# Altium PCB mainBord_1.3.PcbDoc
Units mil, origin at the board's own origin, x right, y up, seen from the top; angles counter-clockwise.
Board outline 3937.01 x 3149.61 mil, 2 copper layers (Top Layer, Bottom Layer); 51 components, 86 nets, 362 pads, 341 vias.
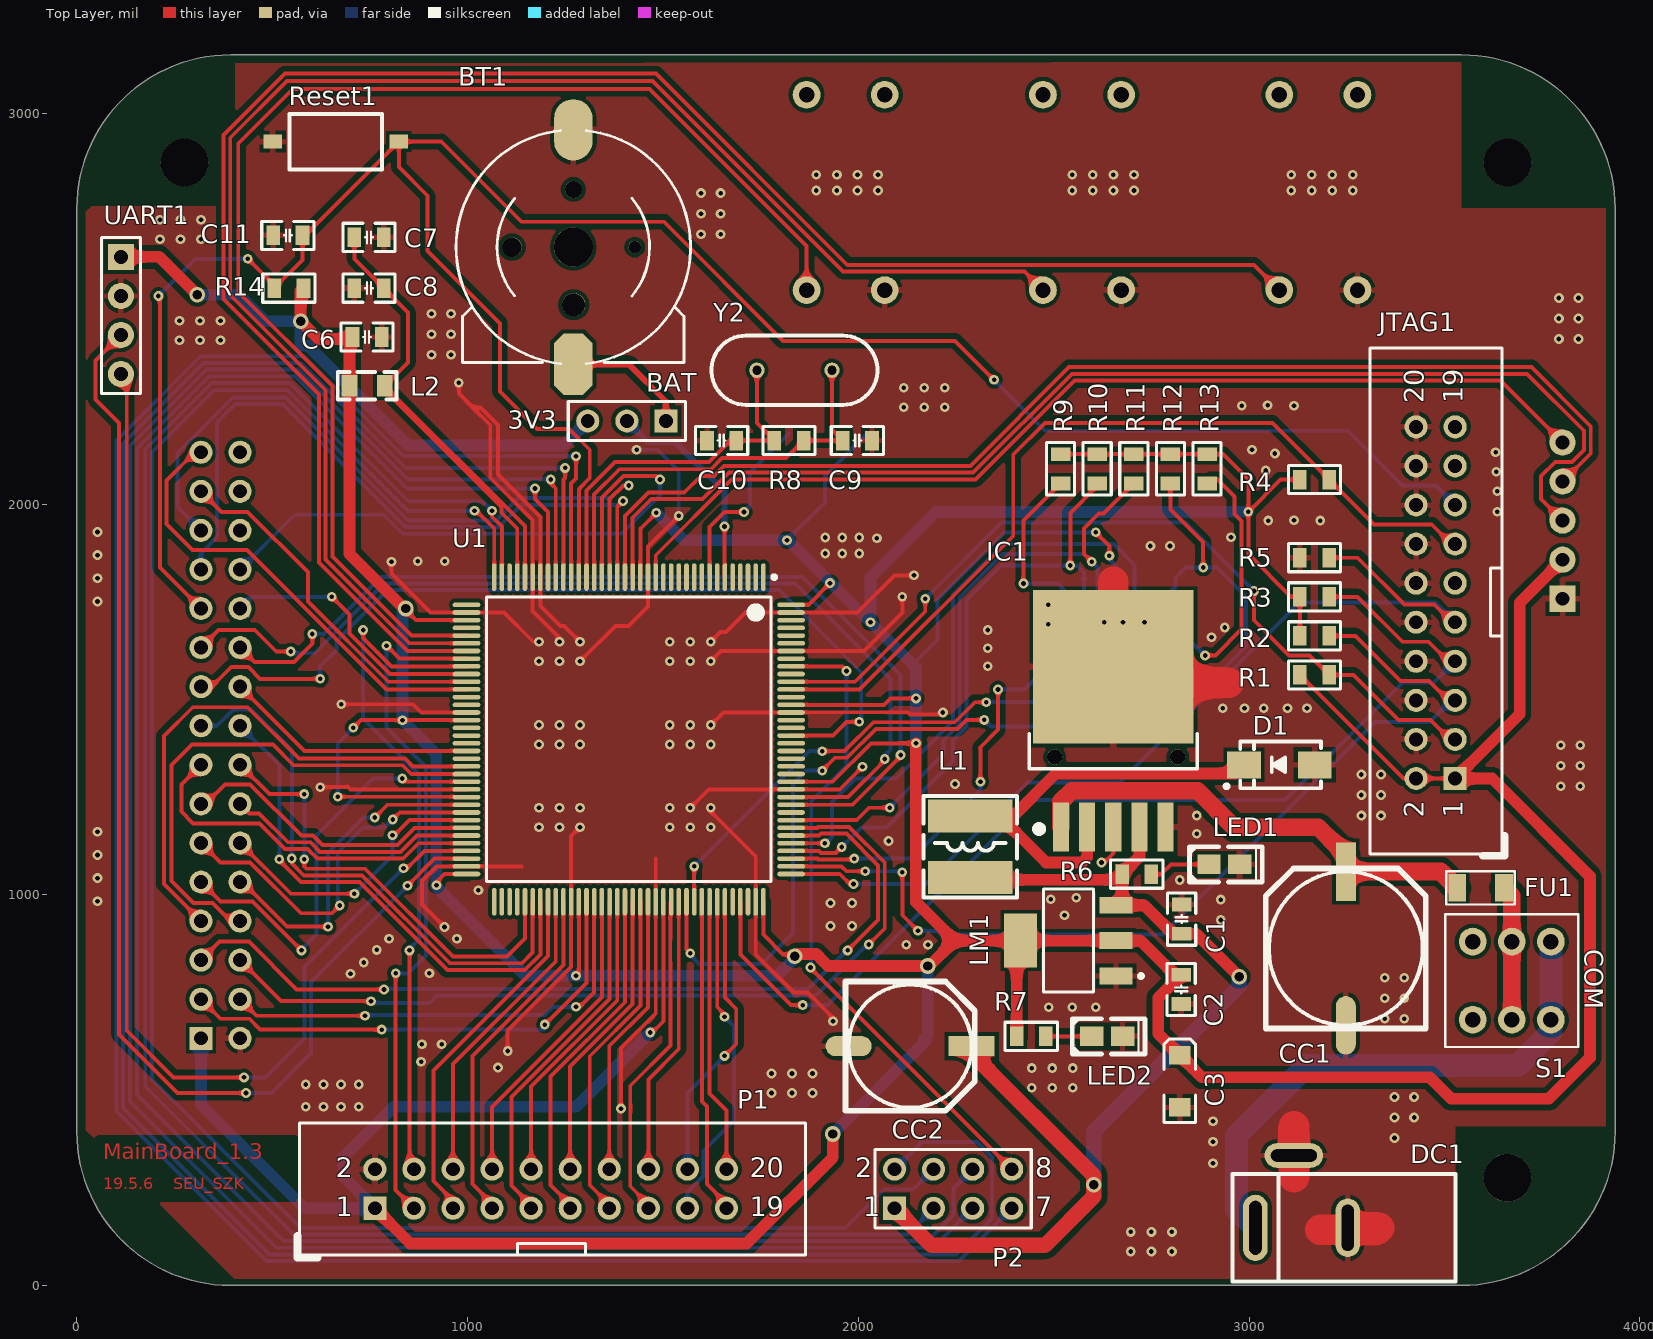
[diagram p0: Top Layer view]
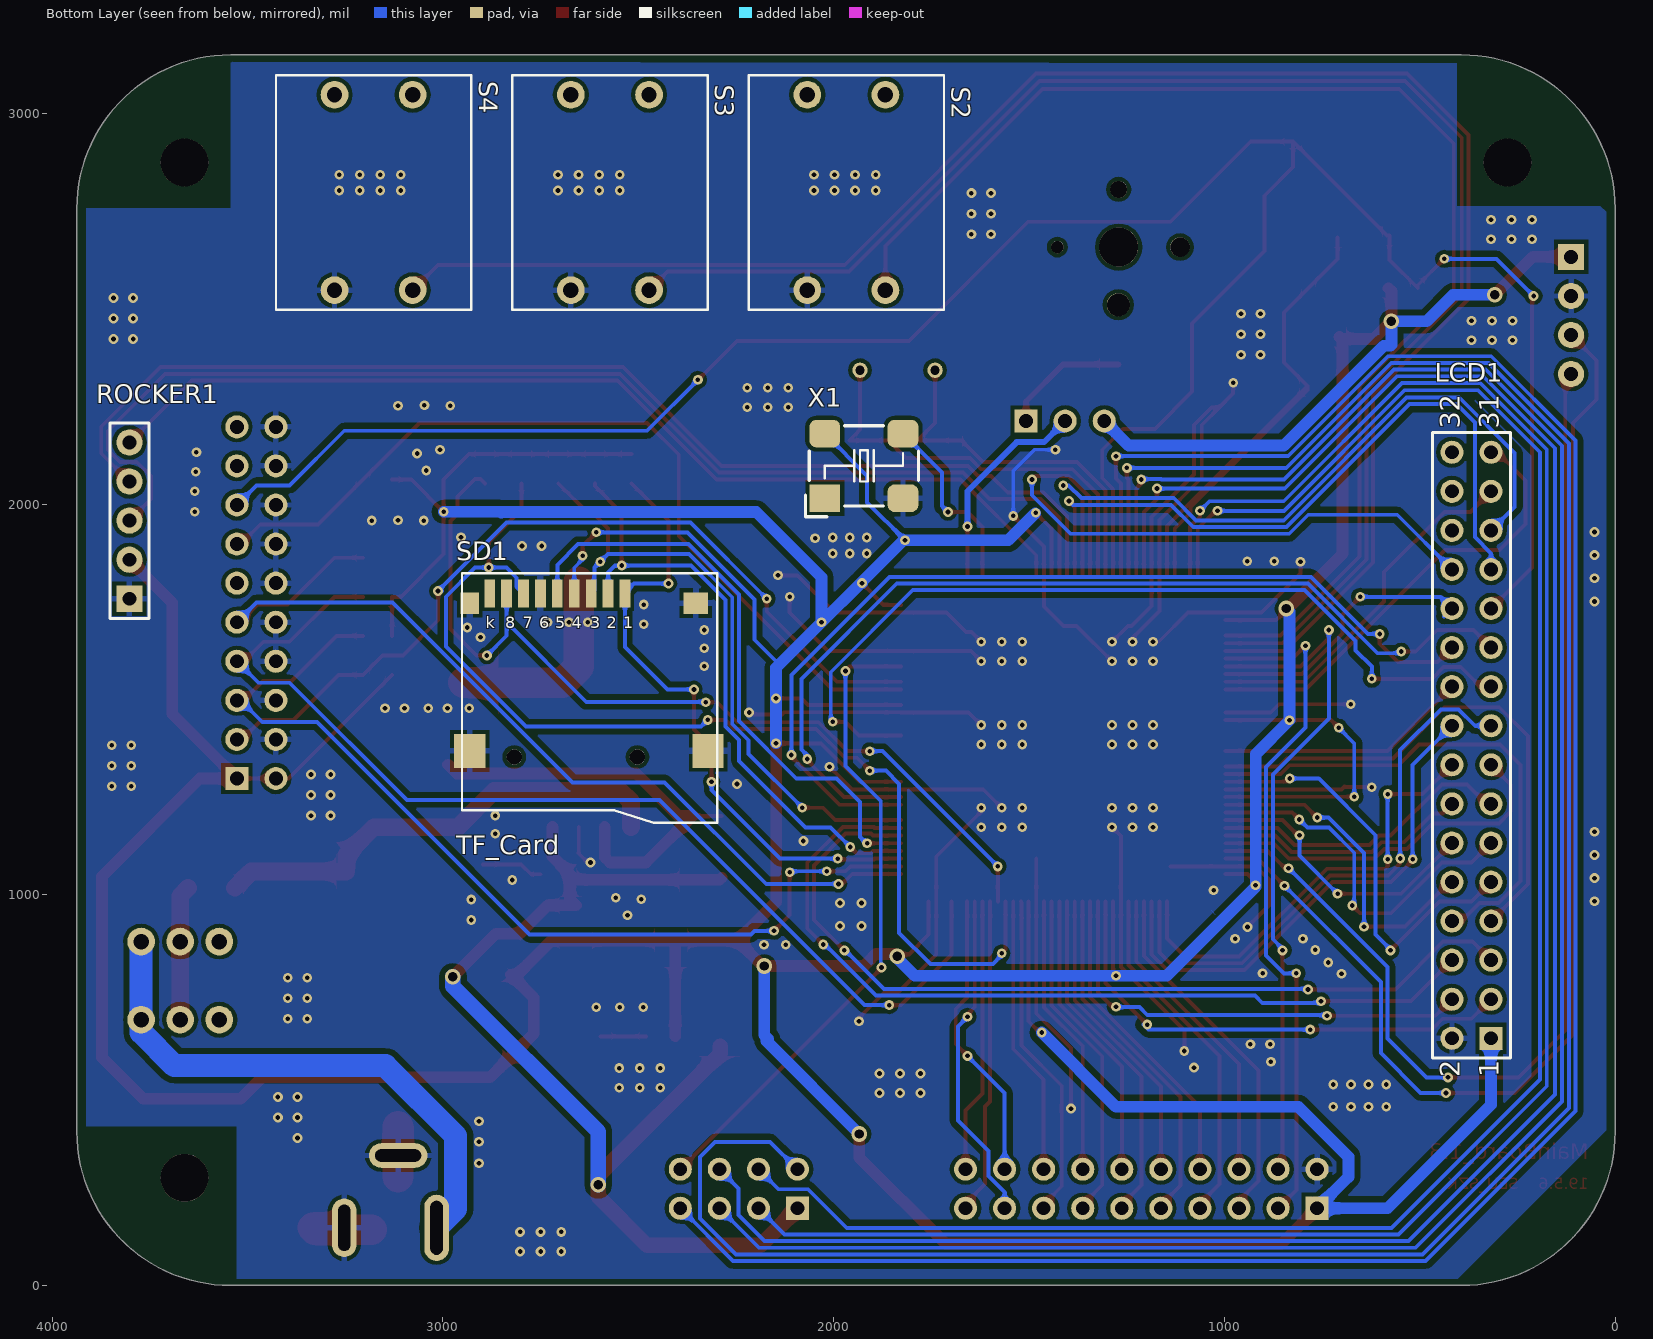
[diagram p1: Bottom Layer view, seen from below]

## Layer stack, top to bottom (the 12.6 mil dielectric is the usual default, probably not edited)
Top Solder: solder mask 0.4, Solder Resist, Dk 3.5
Top Layer: signal copper 1.4
Dielectric 1: dielectric 12.6, FR-4, Dk 4.8
Bottom Layer: signal copper 1.4
Bottom Solder: solder mask 0.4, Solder Resist, Dk 3.5

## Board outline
0,393.7 0,2755.91 cw(c393.7,2755.91) 393.7,3149.61 3543.31,3149.61 cw(c3543.31,2755.91) 3937.01,2755.91 3937.01,393.7 cw(c3543.31,393.7) 3543.31,0 393.7,0 cw(c393.7,393.7)

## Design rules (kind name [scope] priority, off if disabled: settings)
Clearance [InNamedPolygon('GND_L02_P017')] p1: gap=10 ignorepadtopadclearanceinfootprint=FALSE except(0: Arc-Hole Track-Hole SMDPad-Hole THPad-Hole Via-Hole Fill-Hole Poly-Hole Region-Hole Text-Hole; 15: Arc-Fill Arc-Poly Arc-Region Track-Fill Track-Poly Track-Region)
Clearance putuo [InNamedPolygon('Bottom Layer-No Net')] p2: gap=10 ignorepadtopadclearanceinfootprint=FALSE except(0: Arc-Hole Track-Hole SMDPad-Hole THPad-Hole Via-Hole Fill-Hole Poly-Hole Region-Hole Text-Hole; 15: Arc-Fill Arc-Poly Arc-Region Track-Fill Track-Poly Track-Region)
Clearance Clearance_1 [All] p3: gap=7 ignorepadtopadclearanceinfootprint=FALSE except(0: Via-Hole Fill-Hole Poly-Hole Region-Hole Text-Hole)
MinimumSolderMaskSliver [All] p1: minsoldermaskwidth=7
PolygonConnect [All] p1: thpad.connectstyle=Relief thpad.reliefconductorwidth=15 thpad.reliefentries=4 thpad.polygonreliefangle="90 Angle" thpad.airgapwidth=10 smdpad.connectstyle=Relief smdpad.reliefconductorwidth=15 smdpad.reliefentries=4 smdpad.polygonreliefangle="90 Angle" smdpad.airgapwidth=10 via.connectstyle=Direct via.reliefconductorwidth=10 via.reliefentries=4 via.polygonreliefangle="90 Angle" via.airgapwidth=10
RoomDefinition mainBord [InComponentClass('mainBord')] p1: confinementstyle=ConfineIn formatcopy=TRUE lockcomponents=FALSE outline 393.7,3149.61 0,2755.91 0,393.7 393.7,0 3543.31,0 3937.01,393.7 3937.01,2755.91 3543.31,3149.61
RoutingVias [All] p1: holewidth=12 width=25 viastyle="Through Hole" minholewidth=8 minwidth=20 maxholewidth=24 maxwidth=40
SilkToSilkClearance [All] p1 off: silktosilkclearance=10
SilkToSolderMaskClearance [IsPad] p1 off: minsilkscreentomaskgap=10 clearancetoexposedcopper=TRUE
SolderMaskExpansion [All] p1: expansion=4
Width 12V [InNetClass('12V')] p1: maxlimit=78.74 minlimit=39.37 preferedwidth=59.06 minimp=50.000000 maximp=50.000000 favimp=50.000000
Width 5V [InNet('5V')] p2: maxlimit=39.37 minlimit=30 preferedwidth=39.37 minimp=50.000000 maximp=50.000000 favimp=50.000000
Width 3.3V [InNet('3.3V')] p3: maxlimit=39.37 minlimit=10 preferedwidth=30 minimp=50.000000 maximp=50.000000 favimp=50.000000
Width [All] p4: maxlimit=78.74 minlimit=10 preferedwidth=10 minimp=50.000000 maximp=50.000000 favimp=50.000000
27 further rules are at their usual default settings.

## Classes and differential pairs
polygon class PolygonClass_1: GND_L02_P007

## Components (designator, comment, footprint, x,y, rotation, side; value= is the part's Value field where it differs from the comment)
3V3 "Header 3" HDR1X3 1507.6,2212.6 r180 top (schematic designator P3)
BT1 "CR220" battery 1270.95,2556.19 r180 top
C1 "100nf" "C 0805_L" 2827.6,937.6 r90 top value=100nF
C2 "100nf" "C 0805_L" 2826.49,757.6 r270 top value=100nF
C3 "10uf" "CD A(3216)" 2822.6,522.6 r270 top value=10uF
C6 "100nf" "C 0805_L" 742.6,2427.6 r0 top value=100pF
C7 "100nf" "C 0805_L" 747.6,2682.6 r0 top value=100nF
C8 "100nf" "C 0805_L" 747.6,2552.6 r180 top value=100nF
C9 "22pf" "C 0805_L" 1997.6,2162.6 r180 top value=22pF
C10 "22pf" "C 0805_L" 1650.2,2162.6 r0 top value=22pF
C11 "100nf" "C 0805_L" 540.2,2687.6 r0 top value=100nF
CC1 "680uf" "CM F(10*10.2)" 3247.6,862.6 r90 top
CC2 "220uf" "CM E(8*10.2)" 2132.6,612.6 r0 top
D1 "SS14" SMA 3077.6,1332.6 r180 top
DC1 "DC005" DC005座 3252.6,147.6 r180 top
FU1 "200mA" 1206_R 3592.6,1017.6 r180 top
IC1 "LM2596-5.0V" TO263-5A 2652.6,1173.35 r0 top
JTAG1 "JTAG" JTAG20 3527.6,1297.6 r90 top
L1 "Inductor" CD54 2286.66,1122.6 r270 top value=33uH
L2 "Inductor" "L 0805" 742.6,2302.6 r0 top value=4.7uH
LCD1 "TFTLCD" HDR2X16 317.6,632.6 r90 bottom
LED1 "LED2" LED-0805 2897.6,1077.6 r0 top
LED2 "LED2" LED-0805 2597.6,637.6 r0 top
LM1 "LM1117DT-3.3" SOT-223 2537.6,882.6 r90 top
P1 "OUT1" JTAG20 762.6,197.6 r0 top
P2 "OUT2" HDR2X4 2092.6,197.6 r0 top
R1 "10K" "R 0805_L" 3167.6,1562.6 r180 top
R2 "10K" "R 0805_L" 3167.6,1662.6 r180 top
R3 "10K" "R 0805_L" 3167.6,1762.6 r180 top
R4 "10K" "R 0805_L" 3167.6,2062.6 r180 top
R5 "10K" "R 0805_L" 3167.6,1862.6 r0 top
R6 "1K" "R 0805_L" 2712.6,1052.6 r180 top
R7 "1K" "R 0805_L" 2442.6,637.6 r180 top
R8 "1M" "R 0805_L" 1822.6,2162.6 r0 top
R9 "5K" "R 0805_L" 2517.6,2090.19 r270 top
R10 "5K" "R 0805_L" 2611.35,2090.19 r270 top
R11 "5K" "R 0805_L" 2705.1,2090.19 r270 top
R12 "5K" "R 0805_L" 2798.85,2090.19 r270 top
R13 "5K" "R 0805_L" 2892.6,2090.19 r270 top
R14 "1K" "R 0805_L" 542.6,2552.6 r0 top
Reset1 "SW-PB" switch_1 662.6,2927.6 r180 top
ROCKER1 "RK" HDR2.54-M-LI-5P 3802.6,1957.6 r90 bottom
S1 "SW-DPDT" 按键开关-1 3772.6,880.2 r180 top
S2 "SW-PB" 微动开关-大-1-绿 2067.6,2547.6 r180 bottom
S3 "SW-PB" 微动开关-大-1-绿 2672.6,2547.6 r180 bottom
S4 "SW-PB" 微动开关-大-1-绿 3277.6,2547.6 r180 bottom
SD1 "TF_Card" "Micro SD" 2660.08,1352.6 r180 bottom
U1 "STM32F103ZET6" STM-LQFP144_N 1412.6,1397.6 r270 top
UART1 "Header 4" HDR2.54-LI-4P 112.6,2482.6 r270 top
X1 "32.768k" "OSC 7050-4P" 1922.6,2097.6 r180 bottom
Y2 "XTAL" HC-49S 1836.54,2342.6 r0 top

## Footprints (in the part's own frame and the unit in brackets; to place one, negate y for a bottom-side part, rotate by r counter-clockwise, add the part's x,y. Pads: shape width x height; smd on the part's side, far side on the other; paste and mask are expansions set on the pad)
1206_R [mil]
  rect 45x70 smd: 1(-60,0) 2(60,0)
  silkscreen extent -88,-43 88,43, body extent -71,-28 71,28, height 30
battery [mm]
  round 0.813 hole 0.813: 0(-3.979,-2.576)
  round 1.5 hole 1.5: 0(-0.016,1.174)
  round 2.54 hole 2.54: 0(0.009,-2.576)
  round 1.1 hole 1.1: 0(0.009,-6.326)
  round 1.27 hole 1.27: 0(3.997,-2.576)
  oct 2.5x4 smd: GBAT(0.009,5.044)
  oval 2.5x4 smd: VBAT(0.009,-10.196)
  silkscreen extent -7.61,-10.15 7.63,5
"C 0805_L" [mil] "无极性贴片电容"
  rect 35x50 smd: 1(-37.4,0) 2(37.4,0)
  silkscreen extent -67,-36 67,36, body extent -39,-24 39,24, height 20
CD54 [mm] "5.8*5.2*4.5mm（长宽高）"
  rect 2.15x5.5 smd: 1(-2,0) 2(2,0)
  silkscreen extent -3.3,-3.05 3.3,3.05, body extent -2.87,-2.5 2.87,2.5, height 4
"CD A(3216)" [mm] "长3.2mm，宽1.6mm，厚1.6mm"
  rect 1.2x1.4 smd: 1(-1.7,0) 2(1.7,0)
  silkscreen extent -2.74,-1.02 2.67,1.02, body extent -1.6,-0.8 1.6,0.8, height 1.6
"CM E(8*10.2)" [mm] "贴片电解电容，直径8mm，高10.2mm"
  rect 3x1.3 smd: 1(4,0)
  oval 3x1.3 smd: 2(-4,0)
  silkscreen extent -4.2,-4.2 4.2,4.2, body extent -4.5,-4.15 4.5,4.15, height 10.2
"CM F(10*10.2)" [mm] "贴片电解电容，直径10mm，高10.2mm"
  rect 3.8x1.3 smd: 1(5,0)
  oval 3.8x1.3 smd: 2(-5,0)
  silkscreen extent -5.2,-5.2 5.2,5.2, body extent -5.8,-5.15 5.8,5.15, height 10.2
DC005座 [mm]
  oval 3.8x1.6 hole 0.8 slot 3 at 0 deg: CON(3.5,-4.7)
  oval 1.6x3.8 hole 0.8 slot 3 at 90 deg: GND(0,0)
  oval 1.6x4.3 hole 0.8 slot 3.5 at 90 deg: VCC(6,0)
  silkscreen extent -7,-3.5 7.49,3.5
HC-49S [mm]
  round 1 hole 0.6: XTAL_1(-2.44,0) XTAL_2(2.44,0)
  silkscreen extent -5.4,-2.25 5.4,2.25
HDR1X3 [mm] "Connector; Header; 3 Position"
  rect 1.5x1.5 hole 0.9: 1(0,0)
  round 1.5 hole 0.9: 2(2.54,0) 3(5.08,0)
  silkscreen extent -1.27,-1.27 6.35,1.27
HDR2.54-LI-4P [mm] "排针，4脚"
  rect 1.7x1.7 hole 0.9: 1(-3.81,0)
  round 1.7 hole 0.9: 2(-1.27,0) 3(1.27,0) 4(3.81,0)
  silkscreen extent -5.08,-1.27 5.08,1.27, body extent -5.08,-1.27 5.08,1.27, height 8.5
HDR2.54-M-LI-5P [mm] "排母，5脚"
  rect 1.7x1.7 hole 0.9: 1(-5.08,0)
  round 1.7 hole 0.9: 2(-2.54,0) 3(0,0) 4(2.54,0) 5(5.08,0)
  silkscreen extent -6.35,-1.27 6.35,1.27, body extent -6.35,-1.27 6.35,1.27, height 8.5
HDR2X4 [mm] "Connector; Header; 4x2 Position"
  rect 1.5x1.5 hole 0.9: 1(0,0)
  round 1.5 hole 0.9: 2(0,2.54) 3(2.54,0) 4(2.54,2.54) 5(5.08,0) 6(5.08,2.54) 7(7.62,0) 8(7.62,2.54)
  silkscreen extent -1.27,-1.27 8.89,3.81
HDR2X16 [mm] "Connector; Header; 16x2 Position"
  rect 1.5x1.5 hole 0.9: 1(0,0)
  round 1.5 hole 0.9: 2(0,2.54) 3(2.54,0) 4(2.54,2.54) 5(5.08,0) 6(5.08,2.54) 7(7.62,0) 8(7.62,2.54) 9(10.16,0) 10(10.16,2.54) 11(12.7,0) 12(12.7,2.54) 13(15.24,0) 14(15.24,2.54) 15(17.78,0) 16(17.78,2.54) 17(20.32,0) 18(20.32,2.54) 19(22.86,0) 20(22.86,2.54) 21(25.4,0) 22(25.4,2.54) 23(27.94,0) 24(27.94,2.54) 25(30.48,0) 26(30.48,2.54) 27(33.02,0) 28(33.02,2.54) 29(35.56,0) 30(35.56,2.54) 31(38.1,0) 32(38.1,2.54)
  silkscreen extent -1.27,-1.27 39.37,3.81
JTAG20 [mm]
  rect 1.5x1.5 hole 0.9: 1(0,0)
  round 1.5 hole 0.9: 2(0,2.54) 3(2.54,0) 4(2.54,2.54) 5(5.08,0) 6(5.08,2.54) 7(7.62,0) 8(7.62,2.54) 9(10.16,0) 10(10.16,2.54) 11(12.7,0) 12(12.7,2.54) 13(15.24,0) 14(15.24,2.54) 15(17.78,0) 16(17.78,2.54) 17(20.32,0) 18(20.32,2.54) 19(22.86,0) 20(22.86,2.54)
  silkscreen extent -5.03,-3.23 27.99,5.54, body extent -5.01,-3.18 27.99,5.62, height 10.9
"L 0805" [mil] "小功率贴片电感"
  rect 40x55 smd: 1(-45,0) 2(45,0)
  silkscreen extent -75,-35 75,35, body extent -39,-24 39,24, height 35
LED-0805 [mil]
  rect 60x50 smd: 1(0,0) 2(78.74,0)
  silkscreen extent -50,-45 136,45
"Micro SD" [mm]
  round 1 hole 1 unplated: 0(-4,0) 0(4,0)
  rect 0.7x1.8 smd: 1(3.2,10.627) 2(2.1,10.627) 3(1,10.627) 4(-0.1,10.627) 5(-1.2,10.627) 6(-2.3,10.627) 7(-3.4,10.627) 8(-4.5,10.627) 9(-5.6,10.627)
  rect 2.032x2.2 smd: 10(-6.9,0.4) 10(8.6,0.4)
  rect 1.2x1.4 smd: 10(-6.9,10)
  rect 1.6x1.4 smd: 10(7.8,10)
  silkscreen extent -7.4,-4.28 9.2,11.94, body extent 0,0 0,0
"OSC 7050-4P" [mm] "7mm*5mm*1.3mm(长*宽*高)"
  rect 2x1.8 smd: 1(-2.54,-2.1)
  rrect50% 2x1.8 smd: 2(2.54,-2.1) 3(2.54,2.1) 4(-2.54,2.1)
  silkscreen extent -3.81,-3.3 3.56,2.61, body extent -3.5,-2.5 3.5,2.5, height 1.36
"R 0805_L" [mil] "1/8W贴片电阻"
  rect 35x50 smd: 1(-37.4,0) 2(37.4,0)
  silkscreen extent -67,-36 67,36, body extent -39,-25 39,25, height 20
SMA [mm] "4.5x2.6*2.2mm（长宽高，不包括引脚）"
  rect 2.2x1.75 smd: 1(-2.3,0) 2(2.3,0)
  silkscreen extent -2.7,-1.52 3.56,1.52, body extent -2.53,-1.3 2.58,1.3, height 2.15
SOT-223 [mm] "SOT-223/SC-73; 4 Leads; Body 6.7 x 7.3 mm, inc. leads (LxW max)"
  rect 1.1x2.15 smd: 1(-2.3,-3.1) 2(0,-3.1) 3(2.3,-3.1)
  rect 3.5x2.15 smd: 4(0,3.1)
  silkscreen extent -3.35,-4.85 3.35,1.63, body extent -3.25,-3.58 3.25,3.38, height 1.65
STM-LQFP144_N [mm] "Thin QFP, 144-Leads, Body 20x20mm, Pitch 0.5mm, IPC Medium Density"
  oval 1.8x0.3 smd: 1(-10.55,8.75) 2(-10.55,8.25) 3(-10.55,7.75) 4(-10.55,7.25) 5(-10.55,6.75) 6(-10.55,6.25) 7(-10.55,5.75) 8(-10.55,5.25) 9(-10.55,4.75) 10(-10.55,4.25) 11(-10.55,3.75) 12(-10.55,3.25) 13(-10.55,2.75) 14(-10.55,2.25) 15(-10.55,1.75) 16(-10.55,1.25) 17(-10.55,0.75) 18(-10.55,0.25) 19(-10.55,-0.25) 20(-10.55,-0.75) 21(-10.55,-1.25) 22(-10.55,-1.75) 23(-10.55,-2.25) 24(-10.55,-2.75) 25(-10.55,-3.25) 26(-10.55,-3.75) 27(-10.55,-4.25) 28(-10.55,-4.75) 29(-10.55,-5.25) 30(-10.55,-5.75) 31(-10.55,-6.25) 32(-10.55,-6.75) 33(-10.55,-7.25) 34(-10.55,-7.75) 35(-10.55,-8.25) 36(-10.55,-8.75) 73(10.55,-8.75) 74(10.55,-8.25) 75(10.55,-7.75) 76(10.55,-7.25) 77(10.55,-6.75) 78(10.55,-6.25) 79(10.55,-5.75) 80(10.55,-5.25) 81(10.55,-4.75) 82(10.55,-4.25) 83(10.55,-3.75) 84(10.55,-3.25) 85(10.55,-2.75) 86(10.55,-2.25) 87(10.55,-1.75) 88(10.55,-1.25) 89(10.55,-0.75) 90(10.55,-0.25) 91(10.55,0.25) 92(10.55,0.75) 93(10.55,1.25) 94(10.55,1.75) 95(10.55,2.25) 96(10.55,2.75) 97(10.55,3.25) 98(10.55,3.75) 99(10.55,4.25) 100(10.55,4.75) 101(10.55,5.25) 102(10.55,5.75) 103(10.55,6.25) 104(10.55,6.75) 105(10.55,7.25) 106(10.55,7.75) 107(10.55,8.25) 108(10.55,8.75)
  oval 0.3x1.8 smd: 37(-8.75,-10.55) 38(-8.25,-10.55) 39(-7.75,-10.55) 40(-7.25,-10.55) 41(-6.75,-10.55) 42(-6.25,-10.55) 43(-5.75,-10.55) 44(-5.25,-10.55) 45(-4.75,-10.55) 46(-4.25,-10.55) 47(-3.75,-10.55) 48(-3.25,-10.55) 49(-2.75,-10.55) 50(-2.25,-10.55) 51(-1.75,-10.55) 52(-1.25,-10.55) 53(-0.75,-10.55) 54(-0.25,-10.55) 55(0.25,-10.55) 56(0.75,-10.55) 57(1.25,-10.55) 58(1.75,-10.55) 59(2.25,-10.55) 60(2.75,-10.55) 61(3.25,-10.55) 62(3.75,-10.55) 63(4.25,-10.55) 64(4.75,-10.55) 65(5.25,-10.55) 66(5.75,-10.55) 67(6.25,-10.55) 68(6.75,-10.55) 69(7.25,-10.55) 70(7.75,-10.55) 71(8.25,-10.55) 72(8.75,-10.55) 109(8.75,10.55) 110(8.25,10.55) 111(7.75,10.55) 112(7.25,10.55) 113(6.75,10.55) 114(6.25,10.55) 115(5.75,10.55) 116(5.25,10.55) 117(4.75,10.55) 118(4.25,10.55) 119(3.75,10.55) 120(3.25,10.55) 121(2.75,10.55) 122(2.25,10.55) 123(1.75,10.55) 124(1.25,10.55) 125(0.75,10.55) 126(0.25,10.55) 127(-0.25,10.55) 128(-0.75,10.55) 129(-1.25,10.55) 130(-1.75,10.55) 131(-2.25,10.55) 132(-2.75,10.55) 133(-3.25,10.55) 134(-3.75,10.55) 135(-4.25,10.55) 136(-4.75,10.55) 137(-5.25,10.55) 138(-5.75,10.55) 139(-6.25,10.55) 140(-6.75,10.55) 141(-7.25,10.55) 142(-7.75,10.55) 143(-8.25,10.55) 144(-8.75,10.55)
  silkscreen extent -10.67,-9.25 9.25,9.58, body extent -10,-10 10,10, height 1.6
switch_1 [mm]
  rect 1.2x0.9 smd: 1(-4.1,0) 2(4.1,0)
  silkscreen extent -3,-1.8 3,1.82
TO263-5A [mm] "263，5脚晶体管"
  rect 1.05x3.2 smd: 1(-3.4,0) 2(-1.7,0) 3(0,0) 4(1.7,0) 5(3.4,0)
  rect 10.45x10 smd: 3(0,10.414)
  silkscreen extent -5.46,-0.33 5.46,6.04, body extent -5,-0.01 5,13.32, height 4.5
微动开关-大-1-绿 [mm]
  round 1.8 hole 1: 1(0,0) 2(0,12.7) 3(5.08,0) 4(5.08,12.7)
  silkscreen extent -3.81,-1.27 8.89,13.97, body extent -3.46,-0.51 8.54,13.37, height 10
按键开关-1 [mm]
  round 1.8 hole 1: 1(0,0) 2(2.54,0) 3(5.08,0) 4(0,5.08) 5(2.54,5.08) 6(5.08,5.08)
  silkscreen extent -1.78,-1.78 6.86,6.86, body extent -1.71,-1.78 6.79,6.72, height 14.5

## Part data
3V3: "Header, 3-Pin"
BT1: library part Battery, "Multicell Battery"
C1 C2 C6 C7 C8 C9 C10 C11: library part Cap, "Capacitor"
C3: library part "Cap Pol2", "Polarized Capacitor (Axial)"
CC1 CC2: library part CAP-T, "贴片铝解电容"
D1: "肖特基二极管"
FU1: library part FUSE
IC1: library part LM2596-5.0, "DC降压芯片"
JTAG1 P1: library part "Header 10X2", "Header, 10-Pin, Dual row"
L1: Manufacturer="Generic Components"
LCD1: library part MHDR2X16, "Header, 16-Pin, Dual row"
LED1 LED2: "Typical RED, GREEN, YELLOW, AMBER GaAs LED"
LM1: "800mA Low-Dropout Linear Regulator, 3-pin TO-252", Manufacturer="National Semiconductor", PackageTopMarking=NSUZXYTT*LM1117*DT-3.3, PowerWise=N
P2: library part "Header 4X2", "Header, 4-Pin, Dual row"
R1 R2 R3 R4 R5 R6 R7 R8 R9 R10 R11 R12 R13 R14: library part Res2, "Resistor"
Reset1: "Switch"
ROCKER1: library part MHDR1X5, "Header, 5-Pin"
S2 S3 S4: library part 微动开关
SD1: "TF卡座"
U1: "ARM Cortex-M3 32-bit MCU, 512 KB Flash, 64 KB Internal RAM, 112 I/Os, 144-pin LQFP, -40 to 85 degC, Tray", I/Os (High Current)=112, Operating Frequency(F) (Processor speed) (MHz)=72, Supplier Part Number 1=497-6442-ND, Supply Voltage(Vcc) min (V)=2
UART1: "Header, 4-Pin"
X1: library part XTAL-4, "4脚晶振"
Y2: "Crystal Oscillator"

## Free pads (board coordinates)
  round 122.05 hole 122.05 unplated: 2(275.59,2874.02) 3(3661.42,2874.02) 4(3661.42,275.59)

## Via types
v1: diameter 25, hole 12, Top Layer to Bottom Layer, 333 vias
v2: diameter 40, hole 24, Top Layer to Bottom Layer, 8 vias

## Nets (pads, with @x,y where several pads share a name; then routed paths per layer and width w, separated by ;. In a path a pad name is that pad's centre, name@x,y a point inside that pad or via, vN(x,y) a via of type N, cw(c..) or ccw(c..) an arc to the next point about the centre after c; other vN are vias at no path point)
3.3V: 3V3.3 C2.1 C3.1 C6.1 JTAG1.1 JTAG1.2 L2.1 LCD1.1 LM1.2 LM1.4 P1.1 R1.2 R2.2 R3.2 R4.2 R7.2 R9.1 R10.1 R11.1 R12.1 R13.1 R14.2 ROCKER1.2 SD1.4 U1.17 U1.39 U1.52 U1.62 U1.72 U1.84 U1.95 U1.108 U1.121 U1.131 U1.144 UART1.1 X1.4 | length 20624.3
  Top Layer w10: R14.2 R14.2@580.19,2552.59 ; v1(667.6,1250.78) 996.43,1250.78 U1.62 ; v1(707.6,1427.6) 726.81,1446.81 v1(833.39,1446.81) U1.52 ; v2@841.14,1729.18 867.6,1702.72 U1.39 ; v1(920.6,1024.6) 920.6,1032.6 941.11,1053.11 U1.72 ; v1(1277.6,792.6) 1282.6,792.6 1282.6,800.25 1284.65,802.3 U1.84 ; U1.17 1442.13,1937.6 1443.1,1937.6 v1(1483.1,1977.6) ; v1(1467.6,647.6) 1472.6,647.6 1501.18,676.18 U1.95 ; U1.108 1757.09,898.11 1807.6,847.6 1842.6,847.6 v2(1837.6,842.6) ; U1.121 1934.33,1289.33 2032.6,1387.6 v1(2147.6,1387.6) ; U1.131 2065.6,1486.18 2082.02,1502.6 v1(2147.6,1502.6) ; U1.144 1872.09,1742.09 v1(1927.6,1797.6) ; R9.1 R10.1 R11.1 R12.1 R13.1 2933.29,2127.6 2998.18,2062.71 v1@2998.18,1988.14 ; v1(2607.6,1927.6) 2642.6,1892.6 v1(2642.6,1867.6) ; R1.2 3395.21,1297.6 JTAG1.2 JTAG1.1 ; R2.2 R3.2 3107.6,1762.6 2998.18,1872.02 v1(2998.18,1980.11) 3080.68,2062.6 R4.2
  Top Layer w30: UART1.1 210.44,2632.6 v2(307.6,2535.44) ; R14.2 572.6,2545.2 v2(572.6,2467.6) 617.6,2422.6 C6.1@700.2,2422.6 ; C6.1 C6.1@700.2,2422.6 ; P1.1 852.6,107.6 1714.51,107.6 1934.33,327.42 v2(1934.33,387.6) ; v2@839.68,1730.64 697.6,1872.72 L2.1 697.6,2420 C6.1@700.2,2422.6 ; v2@1842.6,847.6 1843.47,848.47 1891.89,848.47 1912.1,828.26 1912.1,828.1 1922.6,817.6 v2(2177.6,817.6) 2177.6,813.88 2246.32,882.6 ; v1(2147.6,1387.6) 2147.33,1387.33 2147.33,981.58 2246.32,882.6 ; R7.2 2405.2,872.25 LM1.4 ; ROCKER1.2 3692.6,1747.6 3692.6,1462.6 JTAG1.1 3622.6,1297.6 3872.6,1047.6 3872.6,582.6 3767.6,477.6 3517.6,477.6 3462.6,532.6 2879.53,532.6 C3.1 2767.6,644.53 2767.6,736.11 C2.1 2810.19,795 2722.6,882.6 LM1.2 LM1.4 ; 2246.32,882.6 LM1.4
  Bottom Layer w10: v1(667.6,1250.78) 667.6,1387.6 v1(707.6,1427.6) ; v1(1817.6,1907.6) 1914.45,2004.45 1914.45,2072.13 X1.4 ; 2142.6,1586.26 2142.6,1592.6 2202.6,1652.6 2202.6,1755.75 2374.45,1927.6 v1(2607.6,1927.6) ; v1(2642.6,1867.6) 2642.6,1858.28 2664.02,1836.86 SD1.4
  Bottom Layer w30: v2(307.6,2535.44) 414.76,2535.44 482.6,2467.6 v2(572.6,2467.6) 572.6,2407.6 575,2405.19 592.23,2405.19 847.82,2149.6 1244.6,2149.6 3V3.3 ; LCD1.1 317.6,462.6 582.6,197.6 P1.1 682.6,277.6 682.6,329.74 810.46,457.6 1277.6,457.6 v1(1467.6,647.6) ; v2(841.64,1732.6) 833.39,1724.34 v1(833.39,1446.81) 920.04,1360.16 v1@920.04,1024.6 ; v1@920.04,1020.16 1147.6,792.6 v1(1277.6,792.6) 1792.6,792.6 1842.6,842.6 v2(1837.6,842.6) ; v1@1484.44,1976.26 1553.1,1907.6 v1(1817.6,1907.6) 1821.26,1907.6 1927.6,1801.26 v1(1927.6,1797.6) 1931.26,1797.6 v1(2031.26,1697.6) ; v2(1934.33,387.6) 2172.6,625.87 2167.6,630.87 2177.6,640.87 v2(2177.6,817.6) ; v1(2147.6,1387.6) v1(2147.6,1502.6) 2147.6,1581.26 2142.6,1586.26 v1(2031.26,1697.6) ; v1(2998.18,1980.11) 2853.29,1980.11 2850.78,1977.6 2848.78,1979.6 2198.26,1979.6 2031.26,1812.6 v1(2031.26,1697.6)
5V: C1.1 CC2.1 IC1.4 L1.2 LM1.3 P2.1 R6.2 | length 2814.9
  Top Layer w30: L1.2 2292.39,1038.13 2660.73,1038.13 R6.2 ; IC1.4 2719.53,1096.93 R6.2 ; v2(2974.6,790.1) 2864.51,900.19 C1.1 2805,900.19 2732.05,973.15 LM1.3 2675.2,988.7 R6.2
  Top Layer w39.37: P2.1 2187.6,102.6 2477.6,102.6 2602.6,227.6 v2(2602.6,257.6) 2602.6,281.25 2290.08,593.77 CC2.1
  Bottom Layer w39.37: v2(2602.6,257.6) 2602.6,393.59 2974.6,765.59 v2(2974.6,790.1)
12V: CC1.1 FU1.2 IC1.1 | length 1218.6
  Top Layer w45: IC1.1 2518.74,1238.74 2545.84,1265.84 2868.31,1265.84 2961.55,1172.6 3177.6,1172.6 3247.6,1102.6 CC1.1 3490.75,1059.45 FU1.2
BL_EN: LCD1.24 U1.46 | length 731
  Top Layer w10: v1(652.6,1762.6) 697.6,1717.6 697.6,1668.54 801.22,1564.92 U1.46
  Bottom Layer w10: LCD1.24@437.6,1712.6 LCD1.24 447.6,1762.6 v1(652.6,1762.6)
DRIVER_OUT1: P1.13 U1.92 | length 859
  Top Layer w10: P1.13 1362.6,207.6 1312.6,257.6 1312.6,586.64 1442.13,716.17 U1.92
DRIVER_OUT2: P1.14 U1.93 | length 725.7
  Top Layer w10: P1.14 1362.6,612.6 1461.81,711.81 U1.93
DRIVER_OUT3: P1.15 U1.96 | length 848.2
  Top Layer w10: P1.15 1462.6,207.6 1416.23,253.96 1416.23,441.59 1417.1,442.45 1417.1,462.75 1416.23,463.61 1416.23,511.24 1519.09,614.09 1519.09,826.84 1518.74,827.19 1518.74,884.79 1519.09,885.14 1519.09,980.46 U1.96
DRIVER_OUT4: P1.16 U1.97 | length 716.9
  Top Layer w10: P1.16 1462.6,527.6 1540.55,605.55 U1.97
DRIVER_OUT5: P1.17 U1.102 | length 860.6
  Top Layer w10: U1.102 1638.98,712.28 1663.66,687.6 v1(1657.6,687.6)
  Bottom Layer w10: P1.17 1562.6,238.87 1604.13,280.4 1604.13,344.13 1682.1,422.1 1682.1,663.1 v1(1657.6,687.6)
DRIVER_OUT6: P1.18 U1.103 | length 748.4
  Top Layer w10: v1(1657.6,587.6) 1687.6,617.6 1687.6,707.6 1658.66,736.53 U1.103
  Bottom Layer w10: P1.18 1562.6,492.6 v1(1657.6,587.6)
DRIVER_PWM1: P1.19 U1.100 | length 810.7
  Top Layer w10: U1.100 1599.61,470.79 1612.6,457.8 1612.6,259.29 1662.6,209.29 P1.19
DRIVER_PWM2: P1.20 U1.101 | length 702.6
  Top Layer w10: U1.101 1619.29,490.9 1662.6,447.6 P1.20
FSMC_A10: LCD1.20 U1.56 | length 647.8
  Top Layer w10: LCD1.20 582.13,1368.07 U1.56
FSMC_D0: LCD1.3 U1.85 | length 1296.3
  Top Layer w10: LCD1.3 367.6,682.6 441.33,682.6 469.08,654.85 v1(780,654.85) ; v1(1197.6,667.6) 1197.6,667.92 1304.33,774.65 U1.85
  Bottom Layer w10: v1(780,654.85) 1194.85,654.85 1207.6,667.6 v1(1197.6,667.6)
FSMC_D1: LCD1.4 U1.86 | length 1181.4
  Top Layer w10: LCD1.4 459.86,690.33 v1(737.6,690.33) ; v1(1277.6,713.27) 1285.93,713.27 1286.6,712.6 1324.02,750.02 U1.86
  Bottom Layer w10: v1(737.6,690.33) 739.36,692.1 1197.45,692.1 1217.7,712.35 1276.68,712.35 v1(1277.6,713.27)
FSMC_D2: LCD1.5 U1.114 | length 2275.2
  Top Layer w10: LCD1.5 365.2,880.2 440,880.2 562.6,757.6 v1(786.1,757.6) ; U1.114 1899.49,1151.53 1904.3,1156.35 1969.61,1156.35 2050.6,1075.36 2050.6,935.6 v1(1972.6,857.6)
  Bottom Layer w10: v1(786.1,757.6) 787.6,759.1 1871.45,759.1 1969.95,857.6 v1(1972.6,857.6)
FSMC_D3: LCD1.6 U1.115 | length 2221.3
  Top Layer w10: LCD1.6 522.6,727.6 v1(752.6,727.6) ; U1.115 1895.13,1171.22 1897.26,1173.35 1976.65,1173.35 2067.6,1082.4 2067.6,913.56 v1(2026.64,872.6)
  Bottom Layer w10: v1(752.6,727.6) 757.1,723.1 903.1,723.1 922.1,742.1 1891.75,742.1 2022.25,872.6 v1(2026.64,872.6)
FSMC_D4: LCD1.7 U1.58 | length 1380.7
  Top Layer w10: LCD1.7 222.6,1027.6 222.6,1406.02 296.55,1479.97 436.42,1479.97 568.01,1348.39 840.5,1348.39 860.19,1328.7 U1.58
FSMC_D5: LCD1.8 U1.59 | length 1322.3
  Top Layer w10: LCD1.8 393.56,932.6 346.93,979.23 298.74,979.23 242.6,1035.37 242.6,1332.6 294.61,1384.61 501.55,1384.61 554.77,1331.39 833.46,1331.39 855.83,1309.02 U1.59
FSMC_D6: LCD1.9 U1.60 | length 1088
  Top Layer w10: LCD1.9 367.6,982.6 449.86,982.6 v1(574.86,857.6) ; v1(832.6,1297.6) 840.87,1289.33 U1.60
  Bottom Layer w10: v1(574.86,857.6) 574.86,859.86 613,898 613,1152.19 758.41,1297.6 v1(832.6,1297.6)
FSMC_D7: LCD1.10 U1.63 | length 866.6
  Top Layer w10: LCD1.10 423.9,1032.6 538.26,918.24 v1(642.6,918.24) ; v1(762.6,1197.6) 795.28,1230.28 U1.63
  Bottom Layer w10: v1(642.6,918.24) 642.6,1106.64 733.56,1197.6 v1(762.6,1197.6)
FSMC_D8: LCD1.11 U1.64 | length 947.2
  Top Layer w10: LCD1.11 367.6,1082.6 443.51,1082.6 573.51,952.6 652.6,952.6 v1(672.6,972.6) ; v1(808.34,1192.6) 826.33,1210.59 U1.64
  Bottom Layer w10: v1(672.6,972.6) 667.6,977.6 667.6,1107.6 732.1,1172.1 787.84,1172.1 v1(808.34,1192.6)
FSMC_D9: LCD1.12 U1.65 | length 742.3
  Top Layer w10: LCD1.12 547.6,1002.6 v1(710.19,1002.6) ; v1(807.6,1152.6) 813.3,1152.6 851.61,1190.91 U1.65
  Bottom Layer w10: v1(710.19,1002.6) 807.6,1100 v1(807.6,1152.6)
FSMC_D10: LCD1.13 U1.66 | length 782.6
  Top Layer w10: LCD1.13 328.62,1232.6 378.62,1282.6 443.56,1282.6 574.86,1151.29 604.63,1151.29 628.33,1127.6 820.66,1127.6 864.28,1171.22 U1.66
FSMC_D11: LCD1.14 U1.67 | length 648
  Top Layer w10: LCD1.14 442.13,1208.07 466.17,1208.07 539.94,1134.29 597.59,1134.29 622.29,1109.6 828.23,1109.6 870.17,1151.53 U1.67
FSMC_D12: LCD1.15 U1.68 | length 936.3
  Top Layer w10: LCD1.15 267.6,1282.6 267.6,1212.6 297.6,1182.6 467.6,1182.6 532.9,1117.29 590.55,1117.29 615.25,1092.6 835.27,1092.6 874.53,1131.85 U1.68
FSMC_D13: LCD1.16 U1.77 | length 1155
  Top Layer w10: LCD1.16 492.6,1257.6 v1(582.13,1257.6) ; v1(582.13,1091.07) 582.13,1072.07 587.6,1066.6 678.34,1066.6 ; 678.37,1066.63 737.17,1066.63 962.19,841.6 1100.85,841.6 1146.85,887.6 U1.77
  Bottom Layer w10: v1(582.13,1091.07) v1(582.13,1257.6)
FSMC_D14: LCD1.17 U1.78 | length 1446.7
  Top Layer w10: v1(550.13,1092.79) 550.13,1080.03 580.56,1049.6 685.38,1049.6 ; 685.41,1049.63 730.12,1049.63 955.15,824.6 1139.18,824.6 1166.54,851.96 U1.78
  Bottom Layer w10: LCD1.17 358.87,1432.6 400.4,1474.13 446.07,1474.13 550.13,1370.07 v1(550.13,1092.79)
FSMC_D15: LCD1.18 U1.79 | length 1321.7
  Top Layer w10: v1(518.13,1091.07) 518.13,1087.99 573.51,1032.6 692.42,1032.6 ; 692.45,1032.63 723.08,1032.63 948.11,807.6 1146.22,807.6 1186.22,847.6 U1.79
  Bottom Layer w10: LCD1.18 518.13,1332.07 v1(518.13,1091.07)
FSMC_NE4: LCD1.19 U1.127 | length 2254.6
  Top Layer w10: LCD1.19 345.09,1532.6 395.09,1582.6 438.82,1582.6 468.82,1552.6 v1(622.6,1552.6) ; U1.127 1935.04,1407.44 1970.2,1442.6 v1(2002.6,1442.6)
  Bottom Layer w10: v1(622.6,1552.6) 622.6,1583.91 664.1,1625.41 664.1,1649.1 794.52,1779.52 1797.65,1779.52 2007.6,1569.57 2007.6,1447.6 v1(2002.6,1442.6)
FSMC_NOE: LCD1.22 U1.118 | length 2454.6
  Top Layer w10: LCD1.22 454.58,1595.62 555.27,1595.62 602.6,1642.95 v1(602.6,1667.6) ; U1.118 1984.92,1230.28 2108.25,1353.6 v1(2108.25,1357.6)
  Bottom Layer w10: v1(602.6,1667.6) 632.6,1667.6 778.52,1813.52 1856.68,1813.52 2108.25,1561.95 v1(2108.25,1357.6)
FSMC_NWE: LCD1.21 U1.119 | length 2476.6
  Top Layer w10: LCD1.21 362.6,1677.6 455.24,1677.6 510.24,1622.6 v1(547.6,1622.6) ; U1.119 1973.54,1249.96 2067.6,1344.02 v1(2067.6,1347.6)
  Bottom Layer w10: v1(547.6,1622.6) 552.1,1618.1 608.1,1618.1 786.52,1796.52 1838.68,1796.52 2082.6,1552.6 2082.6,1371.53 2067.6,1356.53 v1(2067.6,1347.6)
GND: BT1.VBAT C1.2 C2.2 C3.2 C6.2 C7.2 C8.2 C9.1 C10.1 C11.1 CC1.2 CC2.2 D1.1 DC1.CON DC1.GND IC1.3 IC1.5 JTAG1.4 JTAG1.6 JTAG1.8 JTAG1.10 JTAG1.12 JTAG1.14 JTAG1.16 JTAG1.18 JTAG1.20 LCD1.2 LED1.2 LED2.2 LM1.1 P1.2 R5.1 Reset1.2 ROCKER1.1 S2.1 S3.1 S4.1 SD1.6 SD1.10 U1.16 U1.30 U1.31 U1.38 U1.51 U1.61 U1.71 U1.83 U1.94 U1.107 U1.120 U1.130 U1.138 U1.143 UART1.2 X1.2 | length 9212.7
  Top Layer w10: v1(622.6,1275.4) 690.05,1275.4 692.25,1277.6 700.2,1269.65 U1.61 ; v1(676.61,1487.6) 860.17,1487.6 881.27,1466.5 U1.51 ; v1(805.01,1852.6) 805.01,1822.76 905.37,1722.4 U1.38 1093.23,1722.4 1168.03,1647.6 v1(1182.6,1647.6) ; v1(941.11,917.6) 883.73,974.97 883.73,1036.46 920.07,1072.79 U1.71 1137.6,1072.8 ; v1(1102.6,600.24) 1102.6,652.25 1264.96,814.61 U1.83 1264.96,1149.96 v1(1287.6,1172.6) ; v1(1235.1,1647.6) 1235.1,1657.54 1166.54,1726.1 U1.31 1166.54,1958.66 1057.91,2067.28 1057.91,2202.6 1012.91,2247.6 ; v1(1287.6,1597.6) 1378.03,1688.03 1412.24,1688.03 1461.81,1737.6 1461.81,1890.92 v1(1540.55,1969.66) ; v1(1287.6,1647.6) 1247.17,1688.03 1237.6,1688.03 1186.22,1739.41 U1.30 1186.22,1966.81 1077.6,2075.44 1077.6,2202.6 1032.6,2247.6 1012.91,2247.6 ; v1(1392.6,452.6) 1392.6,607.6 1481.5,696.5 U1.94 1481.5,1092.79 ; v1(1570.1,1222.6) 1617.15,1269.65 U1.120 1952.6,1269.65 v1(2010.55,1327.6) ; v1(1622.6,1222.6) 1622.6,1212.35 1737.4,1097.55 U1.107 1737.4,847.6 1835.47,749.53 1870.67,749.53 1935.04,685.15 v1(1935.04,676.18) ; v1(1622.6,1434.61) 1654.49,1466.5 U1.130 ; v1(1622.6,1597.6) 1648.98,1623.98 U1.138 2014.11,1623.98 2014.11,1624.11 2112.6,1722.6 v1(2112.6,1762.6) ; v1(1622.6,1647.6) 1647.6,1672.6 1661.5,1672.6 1711.31,1722.4 U1.143 1997.4,1722.4 2092.6,1817.6 v1(2142.6,1817.6) ; v1(2216.5,1466.5) 2211.68,1461.68 2132.22,1461.68 2126.81,1467.1 U1.130@1828.56,1467.1 ; v1(2622.6,1082.6) 2622.6,1082.49 2626.3,1078.8 2652.6,1105.1 IC1.3@2652.6,1173.35 ; 977.6,2282.91 v1(977.6,2310.19) 977.6,2282.91 ; 977.6,2282.91 1012.6,2247.91 1012.91,2247.6 ; 977.6,2282.91 1012.91,2247.6 ; U1.130 U1.130@1828.56,1467.1 ; U1.130 U1.130@1828.55,1467.1
  Top Layer w78.74: 2652.6,1801.35 2652.6,1583.35 2693.35,1542.6 2947.6,1542.6 ; 3114.8,277.8 DC1.CON 3114.8,407.13 ; 3182.6,142.6 3327.6,142.6 3332.6,147.6 DC1.GND
  Bottom Layer w10: v1(1432.6,2139.02) 1486.18,2139.02 1540.55,2084.65 v1(1540.55,1969.66)
  other v1: 2697.6,87.16 2750.1,87.16 2802.6,87.16 2697.6,137.16 2750.1,137.16 2802.6,137.16 2907.6,312.6 2907.6,367.6 3372.6,377.6 2907.6,420.39 3372.6,430.1 3422.6,430.1 585.76,457.6 630.95,457.19 676.15,457.19 721.34,457.19 3372.6,482.6 3422.6,482.6 1777.6,492.6 1830.1,492.6 1882.6,492.6 2444.14,506.32 2496.64,506.32 2549.14,506.32 585.76,514.14 630.95,514.14 676.15,514.14 721.34,514.14 1777.6,542.6 1830.1,542.6 1882.6,542.6 2444.14,556.32 2496.64,556.32 2549.14,556.32 1077.6,557.6 881.02,572.6 883.05,617.6 933.45,617.6 3347.6,682.6 3397.6,682.6 2487.6,712.28 2547.6,712.28 2607.6,712.28 3347.6,735.1 3397.6,735.1 3347.6,787.6 3397.6,787.6 700.2,797.6 902.23,798.98 733.99,826.84 767.6,858.93 2122.6,872.25 2178.6,872.25 799.13,887.6 972.6,887.6 1928.61,919.86 1983.82,919.86 2927.6,935.6 2527.6,947.6 1928.61,979.13 1983.82,979.13 52.6,983.28 2927.6,987.6 2492.6,988.7 2557.6,992.6 1027.6,1011.58 2822.6,1037.6 52.6,1042.6 52.6,1101.92 2077.6,1137.6 2866.4,1156.06 52.6,1161.24 1182.6,1172.6 1235.1,1172.6 1517.6,1172.6 1570.1,1172.6 1622.6,1172.6 2866.12,1202.6 3287.6,1202.6 3337.6,1202.6 1182.6,1222.6 1235.1,1222.6 1287.6,1222.6 1517.6,1222.6 3287.6,1255.1 3337.6,1255.1 3797.6,1277.6 3847.6,1277.6 2247.6,1283.56 3287.6,1307.6 3337.6,1307.6 3797.6,1330.1 3847.6,1330.1 3797.6,1382.6 3847.6,1382.6 1182.6,1384.61 1235.1,1384.61 1287.6,1384.61 1517.6,1384.61 1570.1,1384.61 1622.6,1384.61 1182.6,1434.61 1235.1,1434.61 1287.6,1434.61 1517.6,1434.61 1570.1,1434.61 2932.6,1477.6 2988.63,1477.6 3037.6,1477.6 3098.63,1477.6 3148.63,1477.6 2331.38,1584.61 1182.6,1597.6 1235.1,1597.6 1517.6,1597.6 1570.1,1597.6 2331.38,1631.1 1517.6,1647.6 1570.1,1647.6 2903.82,1658.79 2331.38,1677.6 2937.6,1684 2486.39,1692.6 2629.62,1697.6 2677.6,1697.6 2732.6,1697.6 2486.39,1742.6 52.6,1750.67 52.6,1809.99 872.6,1853.6 941.61,1853.6 52.6,1869.31 1915.44,1873.4 1958.82,1873.4 2002.2,1873.4 2747.6,1892.6 2797.6,1892.6 2047.6,1912.6 1915.44,1914.23 1958.82,1914.23 2002.2,1914.23 2953.7,1915.25 52.6,1928.63 3049.23,1957.6 3182.6,1957.6 3115.27,1958.39 3635.26,1980.11 3635.26,2032.6 3632.6,2082.6 3042.6,2086.1 3066.26,2129.6 3631.18,2132.6 3007.6,2138.74 2116.5,2247.6 2169,2247.6 2221.5,2247.6 2981.56,2251.81 3114.93,2251.81 3047.6,2252.6 2116.5,2297.6 2169,2297.6 2221.5,2297.6 907.6,2381.89 957.6,2381.89 262.6,2419 315.1,2419 367.6,2419 3793.06,2422.6 3843.06,2422.6 907.6,2434.39 957.6,2434.39 262.6,2469 315.1,2469 367.6,2469 3793.06,2475.1 3843.06,2475.1 907.6,2486.89 957.6,2486.89 3793.06,2527.6 3843.06,2527.6 212.6,2677.6 265.1,2677.6 317.6,2677.6 1597.6,2690.78 1647.6,2690.78 212.6,2727.6 265.1,2727.6 317.6,2727.6 1597.6,2743.28 1647.6,2743.28 1597.6,2795.78 1647.6,2795.78 1892.6,2802.6 1945.22,2802.6 1997.85,2802.6 2050.47,2802.6 2547.6,2802.6 2600.22,2802.6 2652.85,2802.6 2705.47,2802.6 3107.86,2802.6 3160.49,2802.6 3213.11,2802.6 3265.74,2802.6 1892.6,2842.6 1945.22,2842.6 1997.85,2842.6 2050.47,2842.6 2547.6,2842.6 2600.22,2842.6 2652.85,2842.6 2705.47,2842.6 3107.86,2842.6 3160.49,2842.6 3213.11,2842.6 3265.74,2842.6
JNTRST: JTAG1.3 R1.1 U1.134 | length 2171.9
  Top Layer w10: U1.134 1991.19,1545.24 2171.26,1725.3 v1(2171.26,1757.6) ; v1(3012.6,1777.6) 3012.6,1702.6 3102.6,1612.6 3155.01,1612.6 R1.1 3267.59,1562.6 3382.6,1447.6 3464.18,1447.6 3514.18,1397.6 JTAG1.3
  Bottom Layer w10: v1(2171.26,1757.6) 2366.26,1952.6 2837.6,1952.6 v1(3012.6,1777.6) v1@3001.84,1777.6
JTCK: JTAG1.9 R5.2 U1.109 | length 2420.1
  Top Layer w10: U1.109 1952.6,1053.11 1978.11,1027.6 v1(1987.6,1027.6) ; R5.2 3277.6,1862.6 3397.6,1742.6 3474.18,1742.6 3519.17,1697.6 JTAG1.9
  Bottom Layer w10: v1(1987.6,1027.6) 2172.6,1027.6 2432.6,1287.6 2668.7,1287.6 3128.7,1747.6 3477.6,1747.6 JTAG1.9
JTDI: JTAG1.5 R2.1 U1.110 | length 2475.7
  Top Layer w10: U1.110 1956.96,1072.79 1969.56,1060.19 v1(2017.6,1060.19) ; v1(2112.6,1057.6) 2112.6,947.6 v1(2152.6,907.6) ; R2.1 3272.6,1662.6 3387.6,1547.6 3460.55,1547.6 3510.55,1497.6 JTAG1.5
  Bottom Layer w10: v1(2017.6,1060.19) 2110.01,1060.19 v1(2112.6,1057.6) ; v1(2152.6,907.6) 2202.6,907.6 2212.09,898.11 2778.11,898.11 3322.6,1442.6 3462.6,1442.6 3517.6,1497.6 JTAG1.5
JTDO: JTAG1.13 R4.1 U1.133 | length 2232.6
  Top Layer w10: U1.133 2003.49,1525.55 2396.57,1918.63 2396.57,2126.57 2477.92,2207.92 3059.69,2207.92 R4.1 3320.01,1947.6 3467.6,1947.6 3517.6,1897.6 JTAG1.13
JTMS: JTAG1.7 R3.1 U1.105 | length 2773.5
  Top Layer w10: U1.105 1698.03,847.6 1828.03,717.6 v1(1857.6,717.6) ; R3.1 3277.6,1762.6 3392.6,1647.6 3459.13,1647.6 3509.13,1597.6 JTAG1.7
  Bottom Layer w10: v1(1857.6,717.6) 1920.65,717.6 2445.65,1242.6 3092.6,1242.6 3392.6,1542.6 3472.6,1542.6 JTAG1.7
KEY1: S2.3 U1.41 | length 3375.9
  Top Layer w10: U1.41 856.6,1663.35 653.76,1866.18 653.76,2302.11 413.1,2542.78 413.1,2923.1 552.6,3062.6 1465.55,3062.6 1867.6,2660.55 S2.3
KEY2: S3.3 U1.42 | length 3991.1
  Top Layer w10: U1.42 851.54,1643.66 636.76,1858.44 636.76,2291.27 392.6,2535.44 392.6,2937.6 537.28,3082.28 1473.7,3082.28 1960.96,2595.03 2425.16,2595.03 S3.3
KEY3: S4.3 U1.43 | length 4663.4
  Top Layer w10: U1.43 846.22,1623.98 619.76,1850.44 619.76,2280.44 375.6,2524.6 375.6,2944.64 532.93,3101.97 1481.86,3101.97 1971.79,2612.03 3013.16,2612.03 S4.3
LIMIT_SW1: P1.5 U1.80 | length 926.8
  Top Layer w10: P1.5 962.6,217.6 912.6,267.6 912.6,549.93 1205.91,843.24 U1.80
LIMIT_SW2: P1.6 U1.81 | length 793.6
  Top Layer w10: P1.6 962.6,566.43 1225.59,829.42 U1.81
LIMIT_SW3: P1.7 U1.82 | length 901.7
  Top Layer w10: P1.7 1062.6,209.25 1012.6,259.25 1012.6,587.6 1245.28,820.28 U1.82
LIMIT_SW4: P1.8 U1.87 | length 801.1
  Top Layer w10: P1.8 1062.6,456.85 1343.7,737.95 U1.87
LIMIT_SW5: P1.9 U1.88 | length 909.2
  Top Layer w10: P1.9 1162.6,206.07 1112.6,256.07 1112.6,482.81 1363.39,733.59 U1.88
LIMIT_SW6: P1.10 U1.89 | length 776
  Top Layer w10: P1.10 1162.6,508.76 1383.07,729.24 U1.89
LIMIT_SW7: P1.11 U1.90 | length 884.1
  Top Layer w10: P1.11 1262.6,207.6 1212.6,257.6 1212.6,534.72 1402.76,724.88 U1.90
LIMIT_SW8: P1.12 U1.91 | length 750.9
  Top Layer w10: P1.12 1262.6,560.68 1419.76,717.84 1422.44,720.52 U1.91
NetBT1_1: 3V3.1 BT1.GBAT | length 326.4
  Top Layer w15: BT1.GBAT 1412.6,2357.6 1507.6,2262.6 3V3.1
NetD1_2: D1.2 IC1.2 L1.1 | length 1110.9
  Top Layer w10: L1.1 L1.1@2361.81,1201.34
  Top Layer w30: IC1.2 2585.67,1095.67 2572.6,1082.6 2480.55,1082.6 2361.81,1201.34 2396.34,1201.34 2505.34,1310.34 2964.79,1310.34 D1.2
NetDC1_VCC: DC1.VCC S1.1 S1.4 | length 1402.6
  Bottom Layer w59.06: DC1.VCC 2967.6,196.38 2967.6,382.6 3147.6,562.6 3687.6,562.6 3772.6,647.6 S1.4 S1.1
NetFU1_1: FU1.1 S1.2 S1.5 | length 345.7
  Top Layer w45: FU1.1 3672.6,997.6 S1.2 S1.5
NetLED1_1: LED1.1 R6.1 | length 157.9
  Top Layer w10: R6.1 2775.2,1052.6 2800.2,1077.6 LED1.1
NetLED2_1: LED2.1 R7.1 | length 117.6
  Top Layer w10: R7.1 LED2.1
NRST: C11.2 JTAG1.15 LCD1.23 R14.1 Reset1.1 U1.25 | length 6193.3
  Top Layer w10: v1(208.55,2532.6) 212.6,2528.55 212.6,1837.6 LCD1.23 ; v1(437.6,2627.6) 505.19,2560 R14.1 577.6,2625 C11.2 584.02,2687.6 Reset1.1 ; U1.25 1284.65,2037.6 1287.33,2040.28 1287.33,2041.37 1312.6,2066.64 1312.6,2139.02 1259.02,2192.6 1177.6,2192.6 1082.6,2287.6 1082.6,2462.6 897.6,2647.6 897.6,2789.13 824.02,2862.71 Reset1.1 ; v1(2347.6,2317.95) 2247.95,2417.6 1807.59,2417.6 1502.59,2722.6 1137.6,2722.6 931.65,2928.54 930.71,2927.6 Reset1.1
  Bottom Layer w10: v1(208.55,2532.6) 303.55,2627.6 v1(437.6,2627.6) ; v1(2347.6,2317.95) 2477.95,2187.6 3252.6,2187.6 3392.6,2047.6 3477.6,2047.6 JTAG1.15
OSC1_IN: C9.2 R8.2 U1.23 Y2.XTAL_2 | length 1096.1
  Top Layer w10: U1.23 1324.02,2024.02 1389.1,2089.1 1623.14,2089.1 1651.64,2117.6 1815,2117.6 R8.2 C9.2 1932.6,2190.2 Y2.XTAL_2
OSC1_OUT: C10.2 R8.1 U1.24 Y2.XTAL_1 | length 953.9
  Top Layer w10: U1.24 1304.33,2034.33 1377.6,2107.6 1617.6,2107.6 1672.6,2162.6 C10.2 R8.1 1740.47,2207.32 Y2.XTAL_1
OSC32_IN: U1.8 X1.3 | length 480.8
  Top Layer w10: U1.8 1619.29,1941.29 1657.6,1979.6 v1(1707.6,1979.6)
  Bottom Layer w10: v1(1707.6,1979.6) 1722.6,1994.6 1722.6,2080.28 X1.3
RH_DIR: P1.4 U1.45 | length 1779
  Top Layer w10: v1(732.6,1677.6) 732.6,1657.58 805.57,1584.61 U1.45 ; v1(851.54,857.6) 851.54,319.29 846.22,313.98 P1.4
  Bottom Layer w10: v1(732.6,1677.6) 732.6,1451.02 876.04,1307.58 876.04,886.04 847.6,857.6 v1(851.54,857.6)
RH_SPEED: P1.3 U1.44 | length 1769.9
  Top Layer w10: v1(792.6,1637.6) 825.91,1604.29 U1.44 ; v1(815.95,798.98) 815.95,244.25 P1.3
  Bottom Layer w10: v1(792.6,1637.6) 792.6,1427.6 893.04,1327.16 893.04,844.38 847.63,798.98 v1(815.95,798.98)
RK_SW: ROCKER1.5 U1.15 | length 2628.2
  Top Layer w10: U1.15 1481.5,1868.98 1675.12,2062.6 2299.74,2062.6 2553.49,2316.35 3643.85,2316.35 ROCKER1.5
RK_Vx: ROCKER1.3 U1.18 | length 3123.6
  Top Layer w10: U1.18 1422.44,1964.96 1470.08,2012.6 1601.08,2012.6 1669.08,2080.6 2293.7,2080.6 2546.45,2333.35 3711.85,2333.35 3857.6,2187.6 3857.6,2138.74 3826.75,2107.89 3783.81,2107.89 3747.6,2071.68 3747.6,2012.6 ROCKER1.3
RK_Vy: ROCKER1.4 U1.19 | length 3019.6
  Top Layer w10: U1.19 1402.76,1969.32 1463.04,2029.6 1554.6,2029.6 1597.1,2072.1 1630.6,2072.1 1656.1,2097.6 2286.66,2097.6 2539.41,2350.35 3722.69,2350.35 3874.6,2198.44 3874.6,2129.6 ROCKER1.4
SCREW_DIR: P2.5 U1.28 | length 5561.9
  Top Layer w10: v1(1212.6,2062.6) 1212.6,2052.6 1225.59,2039.61 U1.28
  Bottom Layer w10: v1(1212.6,2062.6) 1211.09,2064.11 1162.45,2064.11 1160.94,2062.6 847.6,2062.6 566,2344.19 340.15,2344.19 334.19,2344.19 331.11,2344.19 136.03,2149.11 136.03,471.03 510.46,96.6 2191.6,96.6 P2.5
SCREW_ENABLE: P2.7 U1.26 | length 5908.6
  Top Layer w10: U1.26 1264.96,2052.6 1277.6,2065.24 v1(1277.6,2122.6)
  Bottom Layer w10: v1(1277.6,2122.6) 836.64,2122.6 581.04,2378.19 317.03,2378.19 101.35,2162.52 101.35,446.31 485.06,62.6 2257.6,62.6 P2.7
SCREW_PWM: P2.3 U1.35 | length 5106.5
  Top Layer w10: v1(1062.6,1982.6) 1062.6,1967.6 1087.79,1942.4 U1.35
  Bottom Layer w10: v1(1062.6,1982.6) 1038.1,2007.1 848.1,2007.1 545,2310.19 345.19,2310.19 174.92,2139.92 174.92,509.92 554.24,130.6 2125.6,130.6 P2.3
SD_CLK: SD1.5 U1.113 | length 1534.5
  Top Layer w10: U1.113 v1(1914.45,1131.85)
  Bottom Layer w10: v1(1914.45,1131.85) 1916.85,1131.85 1932.6,1147.6 1932.6,1237.6 1992.6,1297.6 2095.78,1297.6 2242.6,1444.41 2242.6,1768.52 2371.68,1897.6 2654.02,1897.6 2707.32,1844.29 SD1.5
SD_CMD: R11.2 SD1.3 U1.116 | length 1630.6
  Top Layer w10: U1.116 1995.91,1190.91 2027.6,1222.6 v1(2080.2,1222.6) ; v1(2597.6,1852.6) 2577.6,1872.6 2577.6,1937.6 2615.3,1975.3 2627.6,1975.3 R11.2
  Bottom Layer w10: v1(2080.2,1222.6) 2217.6,1360 2217.6,1395.37 2259.6,1437.37 2259.6,1761.48 2370.72,1872.6 2577.6,1872.6 v1(2597.6,1852.6) 2612.6,1837.6 2612.6,1779.09 SD1.3
SD_DATA0: R12.2 SD1.7 U1.98 | length 2795
  Top Layer w10: U1.98 1560.24,859.96 v1(1570.1,850.1) ; v1(1907.6,1317.6) 1940.6,1350.6 1971.56,1350.6 2045.56,1424.6 2253.99,1424.6 2276.99,1447.6 v1(2322.6,1447.6) ; R12.2 2798.85,1986.35 2882.6,1902.6 v1(2882.6,1837.6)
  Bottom Layer w10: v1(1570.1,850.1) 1570.1,845.1 1592.6,822.6 1752.6,822.6 1832.6,902.6 1832.6,1283.56 1866.64,1317.6 v1(1907.6,1317.6) ; v1(2322.6,1447.6) 2339.87,1430.33 2787.39,1430.33 2992.6,1635.54 2992.6,1762.79 2917.79,1837.6 v1(2882.6,1837.6) 2837.68,1837.6 2811.46,1811.39 2811.46,1788.51 SD1.7
SD_DATA1: R13.2 SD1.8 U1.99 | length 2348.2
  Top Layer w10: U1.99 v1(1579.92,1072.6) ; v1(1907.6,1367.6) 1964.52,1367.6 2038.52,1441.6 2246.95,1441.6 2297.95,1492.6 v1(2327.6,1492.6) ; v1(2887.6,1612.6) 2913.81,1612.6 2981.18,1679.97 2981.18,1956.18 2962.6,1974.76 2962.6,2019.61 2918.26,2063.94 2903.74,2063.94 R13.2
  Bottom Layer w10: v1(1579.92,1072.6) 1874.92,1367.6 v1(1907.6,1367.6) ; v1(2327.6,1492.6) 2327.6,1493.6 2633.24,1493.6 2837.24,1697.6 ; SD1.8 2837.24,1697.6 ; v1(2887.6,1612.6) 2837.24,1662.95 2837.24,1697.6
SD_DATA2: R9.2 SD1.1 U1.111 | length 1613.9
  Top Layer w10: U1.111 1895.13,1092.48 1897.26,1090.35 1987.65,1090.35 v1(1989.78,1092.48) ; v1(2312.62,1289.33) 2312.62,1374.9 2311.26,1376.26 2357.6,1422.6 v1(2357.6,1525.55) ; v1(2422.6,1796.52) 2422.6,1957.8 2472.6,2007.8 R9.2
  Bottom Layer w10: v1(1989.78,1092.48) 2137.48,1092.48 2312.62,1267.62 v1(2312.62,1289.33) ; v1(2357.6,1525.55) 2425.55,1525.55 2534.09,1634.09 SD1.1 2534.09,1773.03 2510.61,1796.52 v1(2422.6,1796.52)
SD_DATA3: R10.2 SD1.2 U1.112 | length 1582.3
  Top Layer w10: U1.112 1899.49,1112.16 1904.3,1107.35 1942.66,1107.35 v1(1957.6,1122.28) v1@1962.6,1122.28 ; v1(2542.6,1842.6) 2542.6,1977.6 2611.35,2046.35 R10.2
  Bottom Layer w10: v1(1957.6,1122.28) 2007.91,1172.6 2072.6,1172.6 2242.6,1342.6 2242.6,1396.33 2276.6,1430.33 2276.6,1754.44 2364.76,1842.6 v1(2542.6,1842.6) 2559.87,1842.6 2577.4,1825.07 SD1.2
T_INT: LCD1.26 U1.22 | length 1613.4
  Top Layer w10: U1.22 1343.7,2016.74 1399.06,2072.1 1483.1,2072.1 v1(1492.6,2062.6)
  Bottom Layer w10: LCD1.26 557.6,1972.6 785.47,1972.6 833.97,1924.1 1394.1,1924.1 1492.6,2022.6 v1(1492.6,2062.6)
T_MISO: LCD1.25 U1.20 | length 1816.9
  Top Layer w10: U1.20 1383.07,1993.07 v1(1397.6,2007.6)
  Bottom Layer w10: LCD1.25 317.6,1873.87 359.13,1915.4 359.13,2208.81 405.91,2255.6 526.51,2255.6 841.01,1941.1 1079.79,1941.1 1136.29,1997.6 1387.6,1997.6 v1(1397.6,2007.6) 1397.91,2007.6 v1@1402.76,2012.44
T_MOSI: LCD1.27 U1.21 | length 1868
  Top Layer w10: U1.21 1363.39,1937.6 1363.6,1937.81 1363.6,2012.6 1398.6,2047.6 v1(1412.6,2047.6)
  Bottom Layer w10: LCD1.27 257.24,1992.95 257.24,2130.97 398.87,2272.6 533.56,2272.6 848.06,1958.1 1072.75,1958.1 1129.75,2015.11 1366.11,2015.11 1398.6,2047.6 v1(1412.6,2047.6)
T_SCK: LCD1.29 U1.47 | length 925.5
  Top Layer w10: LCD1.29 370.09,1980.11 437.15,1980.11 591.6,1825.66 591.6,1750.5 796.86,1545.24 U1.47
TP_CS: LCD1.31 U1.48 | length 1172.7
  Top Layer w10: LCD1.31 301.76,2132.6 229.6,2060.44 229.6,1948.42 295.42,1882.6 435.46,1882.6 792.5,1525.55 U1.48
UART3_RX: U1.70 UART1.3 | length 3148.5
  Top Layer w10: UART1.3 47.6,2367.6 47.6,2267.6 107.6,2207.6 107.6,642.6 257.6,492.6 v1(432.6,492.6) ; v1(846.22,1022.99) 915.71,1092.48 U1.70
  Bottom Layer w10: v1(432.6,492.6) 497.6,492.6 599.6,594.6 599.6,776.37 v1(846.22,1022.99)
UART3_TX: U1.69 UART1.4 | length 2961.2
  Top Layer w10: UART1.4 127.6,2332.6 127.6,2257.6 127.6,652.6 247.6,532.6 v1(427.6,532.6) ; v1(835.75,1068.09) 845.5,1068.09 889.57,1112.16 U1.69
  Bottom Layer w10: v1(427.6,532.6) 482.6,532.6 582.6,632.6 582.6,814.94 v1(835.75,1068.09)
VBAT: 3V3.2 U1.6 | length 544.6
  Top Layer w10: v1(1657.6,1942.6) 1657.6,1814.02 U1.6
  Bottom Layer w15: 3V3.2 1461.68,2158.52 1531.68,2158.52 1657.6,2032.6 v1(1657.6,1942.6)
VREF+: C7.1 C8.1 L2.2 U1.32 U1.33 | length 1730.5
  Top Layer w10: C7.1 710.19,2627.41 C8.1 847.6,2490.01 847.6,2362.6 L2.2 ; U1.33 1127.17,1937.6 1087.1,1977.67 1087.1,1992.75 787.6,2292.25 L2.2 ; U1.32 1146.85,1943.35 L2.2
WHEEL_DIR: P2.6 U1.29 | length 5543.9
  Top Layer w10: v1(1172.6,2039.61) 1172.6,2012.6 1205.91,1979.29 U1.29
  Bottom Layer w10: v1(1172.6,2039.61) 845.59,2039.61 558,2327.19 347.19,2327.19 338.15,2327.19 153.71,2142.75 153.71,488.71 528.82,113.6 2176.97,113.6 2243.64,180.28 2243.64,248.64 P2.6 P2.6@2292.6,273.09
WHEEL_ENABLE: P2.2 U1.27 | length 6179.6
  Top Layer w10: U1.27 1245.28,2062.6 1249.6,2066.92 v1(1249.6,2092.6)
  Bottom Layer w10: v1(1249.6,2092.6) 841.64,2092.6 573.04,2361.19 324.07,2361.19 118.35,2155.48 118.35,454.71 493.46,79.6 2250.56,79.6 2342.6,171.64 2342.6,328.34 2303.34,367.6 2162.6,367.6 P2.2
WHEEL_PWM: P2.4 U1.36 | length 5036.9
  Top Layer w10: v1(1017.6,1982.6) 1023.11,1982.6 1068.11,1937.6 U1.36
  Bottom Layer w10: v1(1017.6,1982.6) 847.6,1982.6 538.92,2291.27 351.27,2291.27 192.6,2132.6 192.6,527.6 572.6,147.6 1966.57,147.6 2065.33,246.35 2141.35,246.35 P2.4
WHEEL_SPEED: P2.8 U1.136 | length 1678.4
  Top Layer w10: U1.136 1957.91,1584.61 v1(1969.92,1572.6) ; v1(1877.6,813.97) 1877.6,812.6 P2.8
  Bottom Layer w10: v1(1877.6,813.97) 1877.02,813.97 1872.09,818.9 1879.6,826.41 1879.6,1239.6 1969.92,1329.92 v1(1969.92,1572.6)
pads on no net: BT1.0 JTAG1.11 JTAG1.17 JTAG1.19 LCD1.28 LCD1.30 LCD1.32 S1.3 S1.6 S2.2 S2.4 S3.2 S3.4 S4.2 S4.4 SD1.0 SD1.9 U1.1 U1.2 U1.3 U1.4 U1.5 U1.7 U1.9 U1.10 U1.11 U1.12 U1.13 U1.14 U1.34 U1.37 U1.40 U1.49 U1.50 U1.53 U1.54 U1.55 U1.57 U1.73 U1.74 U1.75 U1.76 U1.104 U1.106 U1.117 U1.122 U1.123 U1.124 U1.125 U1.126 U1.128 U1.129 U1.132 U1.135 U1.137 U1.139 U1.140 U1.141 U1.142 X1.1

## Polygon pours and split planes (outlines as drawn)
GND on Bottom Layer "GND_L02_P017" (solid, remove dead copper, pour order 17): 405.91,3127.6 405.91,2762.6 37.6,2762.6 22.6,2747.6 22.6,397.6 402.6,17.6 3527.6,17.6 3527.6,407.6 3912.6,407.6 3912.6,2757.6 3542.6,2757.6 3542.6,3132.6
GND on Top Layer "Bottom Layer-No Net" (solid, remove dead copper, pour order 20): 405.91,3127.6 405.91,2762.6 37.6,2762.6 22.6,2747.6 22.6,397.6 402.6,17.6 3527.6,17.6 3527.6,407.6 3912.6,407.6 3912.6,2757.6 3542.6,2757.6 3542.6,3132.6

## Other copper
Top Layer:
  pour cut-out: 52.28,385.95 52.28,212.6 562.28,212.6 562.28,385.95
  text "MainBoard_1.3" at 67.21,322.6 h40
  text "19.5.6    SEU_SZK" at 67.21,246.26 h30

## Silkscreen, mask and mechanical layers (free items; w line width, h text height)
Top Overlay:
  text "BAT" at 1457.6,2287.6 h47.24
Top Solder:
  rectangle: 57.6,222.6 552.6,377.6
Mechanical 1:
  the board outline again, w10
